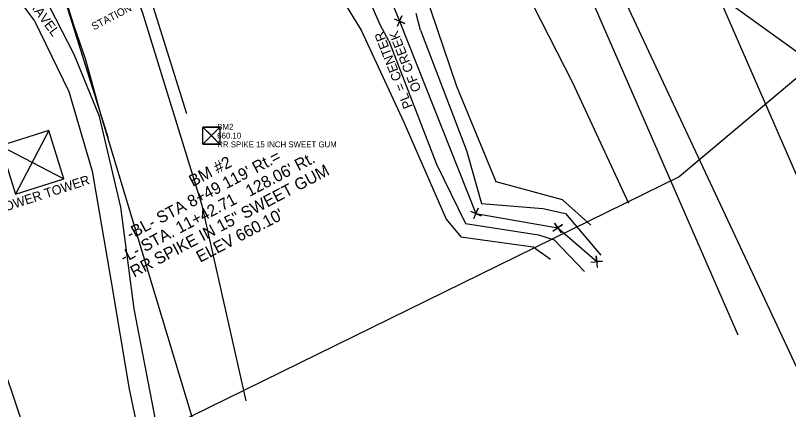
# Model space of a CAD drawing. Extents: x 1380524 to 1382335, y 594765 to 596944.
# Drawn here: x 1381565.9 to 1381895.1, y 595253.4 to 595421 of the extents above; entities that cross this region are included whole.
import ezdxf

# ---------------------------------------------------------------- set-up
doc = ezdxf.new("R2010")
doc.units = 0
for name, color, linetype in [('CTL Bench Mark CELL', 7, 'Continuous'), ('CTL Bench Mark Cogo Comment', 7, 'Continuous'), ('CTL Bench Mark Cogo Elevation', 7, 'Continuous'), ('CTL Bench Mark Cogo Number', 7, 'Continuous'), ('CTL Bench Mark Text', 7, 'Continuous'), ('DTM Contours Major', 7, 'Continuous'), ('Exist Hydro Jurisdictional Stream or Body of Water', 7, 'Continuous'), ('Exist Other Culture Fence Line Text', 7, 'Continuous'), ('Exist Roads EOP', 7, 'Continuous'), ('Exist Structure Major Bridge WW', 7, 'Continuous'), ('Exist Utilities Gas UG Line', 7, 'Continuous'), ('Exist Utilities Gas UG Line SUE', 7, 'Continuous'), ('Exist Utilities Power Tower Text', 7, 'Continuous'), ('Prop Drainage Structure Box Number Symbol CELL', 7, 'Continuous'), ('Prop Drainage Structure Pipe Elbow CELL', 7, 'Continuous'), ('Prop Earthen Structure Cut Ditch Special Detail Label', 7, 'Continuous'), ('Prop Horizontal Alignment Tick Large', 7, 'Continuous'), ('Prop Horizontal Alignment Tick Small', 7, 'Continuous'), ('Prop SS Fill Line', 7, 'Continuous')]:
    doc.layers.add(name, color=color, linetype=linetype)

msp = doc.modelspace()

# ---------------------------------------------------------------- linework, layer by layer
at = {"layer": 'CTL Bench Mark CELL'}
msp.add_line((1381649.29, 595369.92), (1381649.29, 595369.92), dxfattribs=at)
msp.add_lwpolyline([(1381645.7, 595373.51), (1381652.88, 595373.51), (1381652.88, 595366.32), (1381645.7, 595366.32)], close=True, dxfattribs=at)
for points in [[(1381652.88, 595373.51), (1381645.7, 595366.32), (1381649.29, 595369.92), (1381652.88, 595366.32), (1381645.7, 595373.51)], [(1381649.29, 595369.92), (1381652.88, 595373.51), (1381645.7, 595373.51), (1381649.29, 595369.92)], [(1381649.29, 595369.92), (1381645.7, 595366.32), (1381652.88, 595366.32), (1381649.29, 595369.92)]]:
    msp.add_lwpolyline(points, dxfattribs=at)
at = {"layer": 'DTM Contours Major'}
msp.add_lwpolyline([(1381559.46, 595365.58), (1381565.93, 595345.03), (1381586.48, 595351.5), (1381580.02, 595372.05), (1381559.46, 595365.58), (1381586.48, 595351.5), (1381580.02, 595372.05), (1381565.93, 595345.03)], dxfattribs=at)
at = {"layer": 'Exist Hydro Jurisdictional Stream or Body of Water'}
for p, q in [((1381738.37, 595414.72), (1381736.48, 595421.87)), ((1381724.9, 595410.3), (1381721.27, 595416.77))]:
    msp.add_line(p, q, dxfattribs=at)
for points in [[(1381721.27, 595416.77), (1381711.49, 595439.2), (1381704.86, 595458.45), (1381700.71, 595473.32), (1381701.7, 595490.68), (1381690.96, 595508.6), (1381680.33, 595514.31)], [(1381738.37, 595414.72), (1381757.99, 595363.53), (1381764.28, 595341.04), (1381790.41, 595338.9), (1381800.06, 595336.74), (1381815.11, 595319.06)], [(1381724.9, 595410.3), (1381745.21, 595357.82), (1381757.46, 595332.58), (1381788.63, 595327.75), (1381795.23, 595325.63), (1381808.14, 595312.07)]]:
    msp.add_lwpolyline(points, dxfattribs=at)
at = {"layer": 'Exist Roads EOP'}
for p, q in [((1381919.44, 595305.02), (1381827.47, 595515.95)), ((1381873.61, 595285.03), (1381781.63, 595495.96))]:
    msp.add_line(p, q, dxfattribs=at)
for points in [[(1381638.84, 595379.18), (1381451.62, 595975.74)], [(1381605.45, 595368.7), (1381418.22, 595965.25)]]:
    msp.add_lwpolyline(points, dxfattribs=at)
at = {"layer": 'Exist Structure Major Bridge WW'}
for p, q in [((1381729.39, 595418.62), (1381729.39, 595418.62)), ((1381761.92, 595336.77), (1381761.92, 595336.77)), ((1381796.79, 595330.65), (1381796.79, 595330.65)), ((1381813.38, 595316.32), (1381813.38, 595316.32))]:
    msp.add_line(p, q, dxfattribs=at)
for points in [[(1381727.09, 595419.61), (1381731.68, 595417.63), (1381729.39, 595418.62), (1381730.37, 595420.91), (1381728.4, 595416.32)], [(1381759.62, 595337.76), (1381764.22, 595335.78), (1381761.92, 595336.77), (1381762.91, 595339.07), (1381760.93, 595334.48)], [(1381794.74, 595329.21), (1381798.83, 595332.08), (1381796.79, 595330.65), (1381795.35, 595332.7), (1381798.22, 595328.6)], [(1381810.88, 595316.14), (1381815.87, 595316.51), (1381813.38, 595316.32), (1381813.19, 595318.82), (1381813.56, 595313.83)]]:
    msp.add_lwpolyline(points, dxfattribs=at)
at = {"layer": 'Exist Utilities Gas UG Line'}
for points in [[(1381819.69, 595439.52), (1382072.96, 594899.37)], [(1381693.41, 595077.21), (1381602.31, 595378.41)]]:
    msp.add_lwpolyline(points, dxfattribs=at)
at = {"layer": 'Exist Utilities Gas UG Line SUE'}
for p, q in [((1381590.79, 595416.83), (1381587.69, 595426.36)), ((1381595.71, 595402.61), (1381590.79, 595416.83)), ((1381602.31, 595378.41), (1381595.71, 595402.61))]:
    msp.add_line(p, q, dxfattribs=at)
at = {"layer": 'Exist Utilities Power Tower Text'}
for p, q in [((1381713.16, 595459.32), (1381729.39, 595418.62)), ((1381729.39, 595418.62), (1381761.92, 595336.77)), ((1381761.92, 595336.77), (1381796.79, 595330.65)), ((1381796.79, 595330.65), (1381813.38, 595316.32))]:
    msp.add_line(p, q, dxfattribs=at)
at = {"layer": 'Prop Drainage Structure Box Number Symbol CELL'}
msp.add_lwpolyline([(1382083.62, 595964.41), (1382120.69, 595773.82), (1382095.82, 595646.75), (1382010.85, 595488.75), (1381848.52, 595352.32), (1381617.36, 595239.15), (1381304.92, 595184.07), (1381005.77, 595330.75), (1380937.13, 595525.19), (1380768.47, 595849.39), (1380967, 596250.36)], close=True, dxfattribs=at)
at = {"layer": 'Prop Drainage Structure Pipe Elbow CELL'}
for points in [[(1381627.85, 595237.32), (1381616.38, 595296.16), (1381610.74, 595339.43), (1381601.64, 595378.09), (1381590.83, 595404.39), (1381578, 595429.72), (1381569.01, 595443.84), (1381572.14, 595456.07)], [(1381573.88, 595419.06), (1381559.15, 595438.88), (1381546.39, 595446.88)], [(1381573.88, 595419.06), (1381588.64, 595388.63), (1381598.56, 595354.74), (1381606.52, 595308.5), (1381614.24, 595262.08), (1381619.99, 595235.28)]]:
    msp.add_lwpolyline(points, dxfattribs=at)
at = {"layer": 'Prop Earthen Structure Cut Ditch Special Detail Label'}
for points in [[(1381700.88, 595508.12), (1381736, 595527.09), (1381753.67, 595480.99), (1381779.65, 595438.47), (1381803.04, 595392.5), (1381826.97, 595341.11)], [(1381810.86, 595331.84), (1381798.77, 595342.6), (1381770.6, 595350.31), (1381753.89, 595390.83), (1381737.44, 595438.95), (1381720.76, 595467.88), (1381715.91, 595490.83), (1381701.76, 595508)], [(1381909.46, 595397.71), (1381844.05, 595444.77), (1381830.9, 595473.02), (1381914.86, 595485.13), (1381966.96, 595492.75), (1381992.9, 595490.3), (1382011.42, 595478.91)], [(1380970.1, 595427.87), (1381024.06, 595422.83), (1381114.96, 595446.92), (1381185.45, 595457.03), (1381261.8, 595488.06), (1381347.51, 595443.64), (1381414.83, 595426.48), (1381476.71, 595423.61), (1381522.74, 595425.41), (1381550.61, 595301.49), (1381576.12, 595225.45)], [(1381605.49, 595459.01), (1381664.85, 595484.17), (1381691.18, 595450.22), (1381713.09, 595414.76), (1381731.32, 595375.66), (1381749.27, 595334.34), (1381755.49, 595326.83), (1381786.26, 595322.65), (1381793.66, 595317.36)], [(1381664.11, 595257.15), (1381645.41, 595340.23), (1381619.92, 595422.48), (1381605.73, 595458.79)]]:
    msp.add_lwpolyline(points, dxfattribs=at)

# ---------------------------------------------------------------- texts
at = {"layer": 'CTL Bench Mark Cogo Comment'}
msp.add_text('RR SPIKE 15 INCH SWEET GUM', height=2.5, dxfattribs=at).set_placement((1381651.79, 595364.92))
at = {"layer": 'CTL Bench Mark Cogo Elevation'}
msp.add_text('660.10', height=2.5, dxfattribs=at).set_placement((1381651.79, 595368.67))
at = {"layer": 'CTL Bench Mark Cogo Number'}
msp.add_text('BM2', height=2.5, dxfattribs=at).set_placement((1381651.79, 595372.42))
at = {"layer": 'CTL Bench Mark Text'}
for s, p in [("-L- STA. 11+42.71   128.06' Rt.", (1381612.09, 595315.65)), ("-BL- STA 8+49 119' Rt.=", (1381614.76, 595325.54)), ('BM #2 ', (1381641.4, 595348.04)), ('RR SPIKE IN 15" SWEET GUM', (1381616.42, 595309.46)), ("ELEV 660.10'", (1381644.51, 595315.78))]:
    msp.add_text(s, height=5, rotation=27.7735, dxfattribs=at).set_placement(p)
at = {"layer": 'Exist Other Culture Fence Line Text'}
for s, p in [('PL = CENTER', (1381735.09, 595382.32)), ('OF CREEK', (1381738.72, 595389.43))]:
    msp.add_text(s, height=4, rotation=111.6769, dxfattribs=at).set_placement(p)
at = {"layer": 'Prop Horizontal Alignment Tick Large'}
msp.add_text('GRAVEL', height=4, rotation=306.6288, dxfattribs=at).set_placement((1381568.86, 595429.16))
at = {"layer": 'Prop Horizontal Alignment Tick Small'}
msp.add_text('STATION', height=3.2, rotation=27.7977, dxfattribs=at).set_placement((1381599.29, 595414.62))
at = {"layer": 'Prop SS Fill Line'}
msp.add_text('POWER TOWER', height=4, rotation=18.0203, dxfattribs=at).set_placement((1381558.31, 595336.55))

doc.saveas('drawing.dxf')
